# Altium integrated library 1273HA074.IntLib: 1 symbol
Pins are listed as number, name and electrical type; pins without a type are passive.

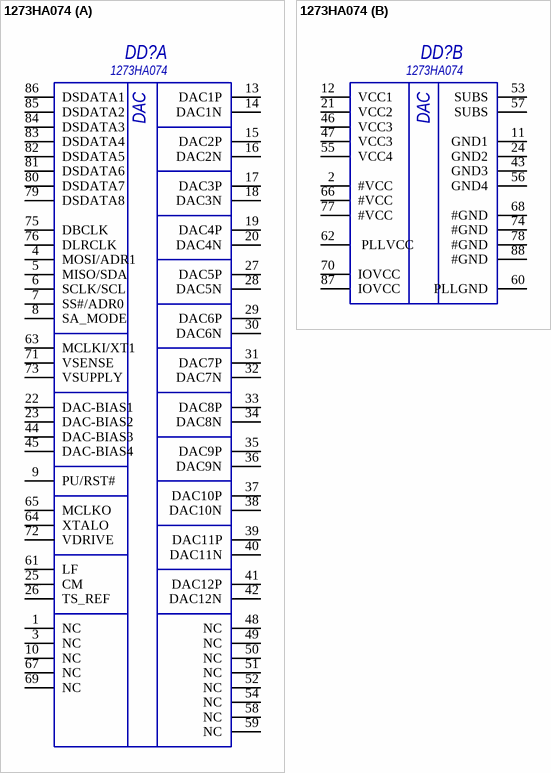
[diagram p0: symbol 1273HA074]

## 1273HA074
designator DD?
Manufacturer: АО"НИИЭТ"; Library Developer: Voronov   (aleksey.voronov.36@yandex.ru)
footprint 4235.88-1
ibis 1273HA084 (Model Description)
part A pins: 1 NC, 3 NC, 4 MOSI/ADR1, 5 MISO/SDA, 6 SCLK/SCL, 7 SS#/ADR0, 8 SA_MODE, 9 PU/RST#, 10 NC, 13 DAC1P, 14 DAC1N, 15 DAC2P, 16 DAC2N, 17 DAC3P, 18 DAC3N, 19 DAC4P, 20 DAC4N, 22 DAC-BIAS1, 23 DAC-BIAS2, 25 CM, 26 TS_REF, 27 DAC5P, 28 DAC5N, 29 DAC6P, 30 DAC6N, 31 DAC7P, 32 DAC7N, 33 DAC8P, 34 DAC8N, 35 DAC9P, 36 DAC9N, 37 DAC10P, 38 DAC10N, 39 DAC11P, 40 DAC11N, 41 DAC12P, 42 DAC12N, 44 DAC-BIAS3, 45 DAC-BIAS4, 48 NC, 49 NC, 50 NC, 51 NC, 52 NC, 54 NC, 58 NC, 59 NC, 61 LF, 63 MCLKI/XT1, 64 XTALO, 65 MCLKO, 67 NC, 69 NC, 71 VSENSE, 72 VDRIVE, 73 VSUPPLY, 75 DBCLK, 76 DLRCLK, 79 DSDATA8, 80 DSDATA7, 81 DSDATA6, 82 DSDATA5, 83 DSDATA4, 84 DSDATA3, 85 DSDATA2, 86 DSDATA1
part B pins: 2 #VCC, 11 GND1, 12 VCC1, 21 VCC2, 24 GND2, 43 GND3, 46 VCC3, 47 VCC3, 53 SUBS, 55 VCC4, 56 GND4, 57 SUBS, 60 PLLGND, 62  PLLVCC, 66 #VCC, 68 #GND, 70 IOVCC, 74 #GND, 77 #VCC, 78 #GND, 87 IOVCC, 88 #GND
